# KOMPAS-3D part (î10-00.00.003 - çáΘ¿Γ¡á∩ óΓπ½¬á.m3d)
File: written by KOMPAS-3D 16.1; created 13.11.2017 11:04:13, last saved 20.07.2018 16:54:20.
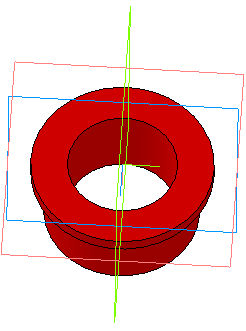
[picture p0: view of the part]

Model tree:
1. Эскиз:1
2. Операция вращения:1
     Угол 1 = 360
3. Фаска:1  (labels: М10-00.00.003)
     Угол = 45; Длина 1 = 0.5; Длина 2 = 0.5

Expressions: 24/2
